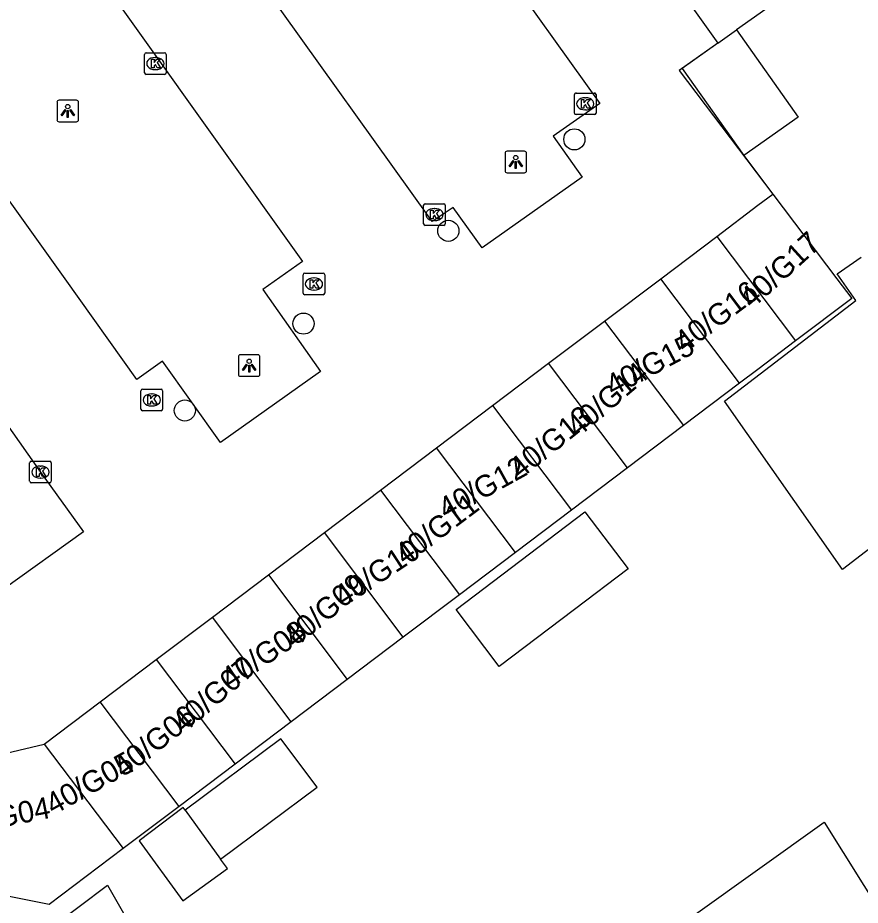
# Model space of a CAD drawing. Extents: x 161845 to 162341, y 381620 to 382158.
# Drawn here: x 161965.76 to 162004.73, y 381971.03 to 382012.07 of the extents above; entities that cross this region are included whole.
import ezdxf

# ---------------------------------------------------------------- set-up
doc = ezdxf.new("R2010")
doc.units = 0
for name, color, linetype in [('IMGEO_Boom', 7, 'Continuous'), ('IMGEO_Kolk', 7, 'Continuous'), ('IMGEO_Lichtpunt', 7, 'Continuous'), ('IMGEO_Muur', 7, 'Continuous'), ('IMGEO_Pand', 7, 'Continuous'), ('IMGEO_Pand_nummerreeks', 7, 'Continuous'), ('IMGEO_Rijbaan_lokaal_open', 7, 'Continuous')]:
    doc.layers.add(name, color=color, linetype=linetype)

msp = doc.modelspace()

# ---------------------------------------------------------------- linework, layer by layer
at = {"layer": 'IMGEO_Boom'}
for centre in [(161991.507, 382006.447), (161985.677, 382002.219), (161978.975, 381997.927), (161973.486, 381993.909)]:
    msp.add_circle(centre, 0.489, dxfattribs=at)
at = {"layer": 'IMGEO_Kolk'}
for p, q in [((161971.621, 382009.529), (161971.621, 382010.381)), ((161971.696, 382010.455), (161972.548, 382010.455)), ((161972.109, 382010.235), (161972.134, 382010.235)), ((161972.622, 382010.381), (161972.622, 382009.529)), ((161972.548, 382009.455), (161971.696, 382009.455)), ((161972.132, 382009.675), (161972.107, 382009.675)), ((161991.584, 382008.593), (161992.436, 382008.593)), ((161991.509, 382007.667), (161991.509, 382008.519)), ((161991.997, 382008.373), (161992.022, 382008.373)), ((161992.51, 382008.519), (161992.51, 382007.667)), ((161992.02, 382007.813), (161991.995, 382007.813)), ((161992.436, 382007.593), (161991.584, 382007.593)), ((161984.535, 382002.546), (161984.535, 382003.398)), ((161984.61, 382003.472), (161985.462, 382003.472)), ((161985.023, 382003.252), (161985.048, 382003.252)), ((161985.536, 382003.398), (161985.536, 382002.546)), ((161985.462, 382002.472), (161984.61, 382002.472)), ((161985.046, 382002.692), (161985.021, 382002.692)), ((161978.96, 381999.334), (161978.96, 382000.186)), ((161979.035, 382000.26), (161979.887, 382000.26)), ((161979.448, 382000.04), (161979.473, 382000.04)), ((161979.961, 382000.186), (161979.961, 381999.334)), ((161979.887, 381999.26), (161979.035, 381999.26)), ((161979.471, 381999.48), (161979.446, 381999.48)), ((161971.458, 381993.971), (161971.458, 381994.823)), ((161971.533, 381994.897), (161972.385, 381994.897)), ((161971.946, 381994.677), (161971.971, 381994.677)), ((161972.459, 381994.823), (161972.459, 381993.971)), ((161972.385, 381993.897), (161971.533, 381993.897)), ((161971.969, 381994.117), (161971.944, 381994.117)), ((161966.308, 381990.635), (161966.308, 381991.487)), ((161966.383, 381991.561), (161967.235, 381991.561)), ((161966.796, 381991.341), (161966.821, 381991.341)), ((161967.309, 381991.487), (161967.309, 381990.635)), ((161967.235, 381990.561), (161966.383, 381990.561)), ((161966.819, 381990.781), (161966.794, 381990.781))]:
    msp.add_line(p, q, dxfattribs=at)
for points in [[(161971.621, 382009.529), (161971.621, 382010.381)], [(161971.696, 382010.455), (161972.548, 382010.455)], [(161972.622, 382010.381), (161972.622, 382009.529)], [(161971.942, 382010.155), (161972.065, 382010.155), (161972.065, 382010.004), (161972.195, 382010.155), (161972.359, 382010.155), (161972.213, 382010.004), (161972.366, 382009.755), (161972.214, 382009.755), (161972.129, 382009.919), (161972.065, 382009.852), (161972.065, 382009.755), (161971.942, 382009.755), (161971.942, 382010.155)], [(161972.548, 382009.455), (161971.696, 382009.455)], [(161991.584, 382008.593), (161992.436, 382008.593)], [(161991.509, 382007.667), (161991.509, 382008.519)], [(161991.83, 382008.293), (161991.953, 382008.293), (161991.953, 382008.142), (161992.083, 382008.293), (161992.247, 382008.293), (161992.101, 382008.142), (161992.254, 382007.893), (161992.102, 382007.893), (161992.017, 382008.057), (161991.953, 382007.99), (161991.953, 382007.893), (161991.83, 382007.893), (161991.83, 382008.293)], [(161992.51, 382008.519), (161992.51, 382007.667)], [(161992.436, 382007.593), (161991.584, 382007.593)], [(161984.535, 382002.546), (161984.535, 382003.398)], [(161984.61, 382003.472), (161985.462, 382003.472)], [(161985.536, 382003.398), (161985.536, 382002.546)], [(161984.856, 382003.172), (161984.979, 382003.172), (161984.979, 382003.021), (161985.109, 382003.172), (161985.273, 382003.172), (161985.127, 382003.021), (161985.28, 382002.772), (161985.128, 382002.772), (161985.043, 382002.936), (161984.979, 382002.869), (161984.979, 382002.772), (161984.856, 382002.772), (161984.856, 382003.172)], [(161985.462, 382002.472), (161984.61, 382002.472)], [(161978.96, 381999.334), (161978.96, 382000.186)], [(161979.035, 382000.26), (161979.887, 382000.26)], [(161979.281, 381999.96), (161979.404, 381999.96), (161979.404, 381999.809), (161979.534, 381999.96), (161979.698, 381999.96), (161979.552, 381999.809), (161979.705, 381999.56), (161979.553, 381999.56), (161979.468, 381999.724), (161979.404, 381999.657), (161979.404, 381999.56), (161979.281, 381999.56), (161979.281, 381999.96)], [(161979.961, 382000.186), (161979.961, 381999.334)], [(161979.887, 381999.26), (161979.035, 381999.26)], [(161971.458, 381993.971), (161971.458, 381994.823)], [(161971.533, 381994.897), (161972.385, 381994.897)], [(161972.459, 381994.823), (161972.459, 381993.971)], [(161971.779, 381994.597), (161971.902, 381994.597), (161971.902, 381994.446), (161972.032, 381994.597), (161972.196, 381994.597), (161972.05, 381994.446), (161972.203, 381994.197), (161972.051, 381994.197), (161971.966, 381994.361), (161971.902, 381994.294), (161971.902, 381994.197), (161971.779, 381994.197), (161971.779, 381994.597)], [(161972.385, 381993.897), (161971.533, 381993.897)], [(161966.308, 381990.635), (161966.308, 381991.487)], [(161966.383, 381991.561), (161967.235, 381991.561)], [(161967.309, 381991.487), (161967.309, 381990.635)], [(161966.629, 381991.261), (161966.752, 381991.261), (161966.752, 381991.11), (161966.882, 381991.261), (161967.046, 381991.261), (161966.9, 381991.11), (161967.053, 381990.861), (161966.901, 381990.861), (161966.816, 381991.025), (161966.752, 381990.958), (161966.752, 381990.861), (161966.629, 381990.861), (161966.629, 381991.261)], [(161967.235, 381990.561), (161966.383, 381990.561)]]:
    msp.add_lwpolyline(points, dxfattribs=at)
for centre, start, end in [((161971.698, 382010.379), 91.552, 178.448), ((161971.698, 382010.379), 91.552, 178.448), ((161972.546, 382010.379), 1.552, 88.448), ((161972.546, 382010.379), 1.552, 88.448), ((161971.698, 382009.531), 181.552, 268.448), ((161971.698, 382009.531), 181.552, 268.448), ((161972.546, 382009.531), 271.552, 358.448), ((161972.546, 382009.531), 271.552, 358.448), ((161991.586, 382008.517), 91.552, 178.448), ((161991.586, 382008.517), 91.552, 178.448), ((161992.434, 382008.517), 1.552, 88.448), ((161992.434, 382008.517), 1.552, 88.448), ((161991.586, 382007.669), 181.552, 268.448), ((161991.586, 382007.669), 181.552, 268.448), ((161992.434, 382007.669), 271.552, 358.448), ((161992.434, 382007.669), 271.552, 358.448), ((161984.612, 382003.396), 91.552, 178.448), ((161984.612, 382003.396), 91.552, 178.448), ((161985.46, 382003.396), 1.552, 88.448), ((161985.46, 382003.396), 1.552, 88.448), ((161984.612, 382002.548), 181.552, 268.448), ((161984.612, 382002.548), 181.552, 268.448), ((161985.46, 382002.548), 271.552, 358.448), ((161985.46, 382002.548), 271.552, 358.448), ((161979.037, 382000.184), 91.552, 178.448), ((161979.037, 382000.184), 91.552, 178.448), ((161979.885, 382000.184), 1.552, 88.448), ((161979.885, 382000.184), 1.552, 88.448), ((161979.037, 381999.336), 181.552, 268.448), ((161979.037, 381999.336), 181.552, 268.448), ((161979.885, 381999.336), 271.552, 358.448), ((161979.885, 381999.336), 271.552, 358.448), ((161971.535, 381994.821), 91.552, 178.448), ((161971.535, 381994.821), 91.552, 178.448), ((161972.383, 381994.821), 1.552, 88.448), ((161972.383, 381994.821), 1.552, 88.448), ((161971.535, 381993.973), 181.552, 268.448), ((161971.535, 381993.973), 181.552, 268.448), ((161972.383, 381993.973), 271.552, 358.448), ((161972.383, 381993.973), 271.552, 358.448), ((161966.385, 381991.485), 91.552, 178.448), ((161966.385, 381991.485), 91.552, 178.448), ((161967.233, 381991.485), 1.552, 88.448), ((161967.233, 381991.485), 1.552, 88.448), ((161966.385, 381990.637), 181.552, 268.448), ((161966.385, 381990.637), 181.552, 268.448), ((161967.233, 381990.637), 271.552, 358.448), ((161967.233, 381990.637), 271.552, 358.448)]:
    msp.add_arc(centre, 0.0765, start, end, dxfattribs=at)
for centre, major_axis, ratio, start_param, end_param in [((161972.108, 382009.955), (-0.387, 0.002), 0.722429, 4.712389, 7.853982), ((161972.133, 382009.955), (-0.39, 0.002), 0.717154, 1.570796, 4.712389), ((161991.996, 382008.093), (-0.387, 0.002), 0.722429, 4.712389, 7.853982), ((161992.021, 382008.093), (-0.39, 0.002), 0.717154, 1.570796, 4.712389), ((161985.022, 382002.972), (-0.387, 0.002), 0.722429, 4.712389, 7.853982), ((161985.047, 382002.972), (-0.39, 0.002), 0.717154, 1.570796, 4.712389), ((161979.447, 381999.76), (-0.387, 0.002), 0.722429, 4.712389, 7.853982), ((161979.472, 381999.76), (-0.39, 0.002), 0.717154, 1.570796, 4.712389), ((161971.945, 381994.397), (-0.387, 0.002), 0.722429, 4.712389, 7.853982), ((161971.97, 381994.397), (-0.39, 0.002), 0.717154, 1.570796, 4.712389), ((161966.795, 381991.061), (-0.387, 0.002), 0.722429, 4.712389, 7.853982), ((161966.82, 381991.061), (-0.39, 0.002), 0.717154, 1.570796, 4.712389)]:
    msp.add_ellipse(centre, major_axis=major_axis, ratio=ratio, start_param=start_param, end_param=end_param, dxfattribs=at)
at = {"layer": 'IMGEO_Lichtpunt'}
for p, q in [((161967.573, 382008.166), (161967.573, 382007.359)), ((161967.573, 382008.166), (161967.573, 382007.359)), ((161968.475, 382008.261), (161967.667, 382008.261)), ((161968.475, 382008.261), (161967.667, 382008.261)), ((161968.569, 382007.359), (161968.569, 382008.166)), ((161968.569, 382007.359), (161968.569, 382008.166)), ((161967.667, 382007.265), (161968.475, 382007.265)), ((161967.667, 382007.265), (161968.475, 382007.265)), ((161988.299, 382005.807), (161988.299, 382005)), ((161988.299, 382005.807), (161988.299, 382005)), ((161989.201, 382005.902), (161988.393, 382005.902)), ((161989.201, 382005.902), (161988.393, 382005.902)), ((161989.295, 382005), (161989.295, 382005.807)), ((161989.295, 382005), (161989.295, 382005.807)), ((161988.393, 382004.906), (161989.201, 382004.906)), ((161988.393, 382004.906), (161989.201, 382004.906)), ((161975.964, 381996.391), (161975.964, 381995.584)), ((161975.964, 381996.391), (161975.964, 381995.584)), ((161976.866, 381996.486), (161976.058, 381996.486)), ((161976.866, 381996.486), (161976.058, 381996.486)), ((161976.96, 381995.584), (161976.96, 381996.391)), ((161976.96, 381995.584), (161976.96, 381996.391)), ((161976.058, 381995.49), (161976.866, 381995.49)), ((161976.058, 381995.49), (161976.866, 381995.49))]:
    msp.add_line(p, q, dxfattribs=at)
for points in [[(161967.947, 382007.83), (161967.986, 382007.802), (161967.798, 382007.54), (161967.76, 382007.567), (161967.947, 382007.83)], [(161968.049, 382007.782), (161968.096, 382007.782), (161968.096, 382007.46), (161968.049, 382007.46), (161968.049, 382007.782)], [(161968.159, 382007.802), (161968.197, 382007.829), (161968.384, 382007.567), (161968.345, 382007.539), (161968.159, 382007.802)], [(161988.673, 382005.471), (161988.712, 382005.443), (161988.524, 382005.181), (161988.486, 382005.208), (161988.673, 382005.471)], [(161988.775, 382005.423), (161988.822, 382005.423), (161988.822, 382005.101), (161988.775, 382005.101), (161988.775, 382005.423)], [(161988.885, 382005.443), (161988.923, 382005.47), (161989.11, 382005.208), (161989.071, 382005.18), (161988.885, 382005.443)], [(161976.338, 381996.055), (161976.377, 381996.027), (161976.189, 381995.765), (161976.151, 381995.792), (161976.338, 381996.055)], [(161976.44, 381996.007), (161976.487, 381996.007), (161976.487, 381995.685), (161976.44, 381995.685), (161976.44, 381996.007)], [(161976.55, 381996.027), (161976.588, 381996.054), (161976.775, 381995.792), (161976.736, 381995.764), (161976.55, 381996.027)]]:
    msp.add_lwpolyline(points, dxfattribs=at)
for centre in [(161968.072, 382007.964), (161988.798, 382005.605), (161976.463, 381996.189)]:
    msp.add_circle(centre, 0.0994, dxfattribs=at)
for centre, start, end in [((161967.667, 382008.166), 90, 180), ((161967.667, 382008.166), 90, 180), ((161968.475, 382008.166), 0, 90), ((161968.475, 382008.166), 0, 90), ((161967.667, 382007.359), 180, 270), ((161967.667, 382007.359), 180, 270), ((161968.475, 382007.359), 270, 0), ((161968.475, 382007.359), 270, 360), ((161988.393, 382005.807), 90, 180), ((161988.393, 382005.807), 90, 180), ((161989.201, 382005.807), 0, 90), ((161989.201, 382005.807), 0, 90), ((161988.393, 382005), 180, 270), ((161988.393, 382005), 180, 270), ((161989.201, 382005), 270, 0), ((161989.201, 382005), 270, 360), ((161976.058, 381996.391), 90, 180), ((161976.058, 381996.391), 90, 180), ((161976.866, 381996.391), 0, 90), ((161976.866, 381996.391), 0, 90), ((161976.058, 381995.584), 180, 270), ((161976.058, 381995.584), 180, 270), ((161976.866, 381995.584), 270, 0), ((161976.866, 381995.584), 270, 360)]:
    msp.add_arc(centre, 0.0946, start, end, dxfattribs=at)
at = {"layer": 'IMGEO_Muur'}
msp.add_lwpolyline([(161998.137, 382010.902), (161996.361, 382009.629), (162000.686, 382003.921)], dxfattribs=at)
at = {"layer": 'IMGEO_Pand'}
for points in [[(162000.99, 382017.333), (162003.079, 382014.393), (161999.002, 382011.513)], [(161996.058, 382013.827), (161998.137, 382010.902)], [(161998.137, 382010.902), (161999.002, 382011.513)], [(161999.002, 382011.513), (162001.865, 382007.483), (161999.348, 382005.705)], [(161998.137, 382010.902), (161996.492, 382009.723), (161999.348, 382005.705)], [(161998.094, 382001.963), (162000.001, 382003.403), (162000.686, 382003.921)], [(162000.686, 382003.921), (162003.65, 382000), (162004.343, 381999.083), (162001.745, 381997.127)], [(161995.501, 382000.006), (161998.094, 382001.963)], [(161998.094, 382001.963), (162001.745, 381997.127)], [(162010.905, 381991.921), (162003.909, 381986.55), (161998.457, 381994.338), (162004.528, 381998.999), (162003.669, 382000.227), (162004.777, 382001.002)], [(161992.908, 381998.048), (161995.501, 382000.006)], [(161999.151, 381995.172), (161995.501, 382000.006)], [(161990.316, 381996.091), (161992.908, 381998.048)], [(161992.908, 381998.048), (161996.558, 381993.215)], [(162001.745, 381997.127), (162000, 381995.813), (161999.151, 381995.172)], [(161987.723, 381994.134), (161990.316, 381996.091)], [(161993.965, 381991.258), (161990.316, 381996.091)], [(161999.151, 381995.172), (161996.558, 381993.215)], [(161985.13, 381992.176), (161987.723, 381994.134)], [(161987.723, 381994.134), (161991.372, 381989.301)], [(161996.558, 381993.215), (161993.965, 381991.258)], [(161982.538, 381990.219), (161985.13, 381992.176)], [(161988.779, 381987.344), (161985.13, 381992.176)], [(161993.965, 381991.258), (161991.372, 381989.301)], [(161979.945, 381988.261), (161982.538, 381990.219)], [(161982.538, 381990.219), (161986.186, 381985.386)], [(161991.372, 381989.301), (161988.779, 381987.344)], [(161991.999, 381989.224), (161993.998, 381986.582), (161991.52, 381984.707), (161988.036, 381982.071), (161986.037, 381984.713), (161991.999, 381989.224)], [(161977.352, 381986.304), (161979.945, 381988.261)], [(161983.593, 381983.429), (161979.945, 381988.261)], [(161988.779, 381987.344), (161986.186, 381985.386)], [(161974.76, 381984.346), (161977.352, 381986.304)], [(161977.352, 381986.304), (161981, 381981.472)], [(161986.186, 381985.386), (161983.593, 381983.429)], [(161972.167, 381982.389), (161974.76, 381984.346)], [(161978.407, 381979.515), (161974.76, 381984.346)], [(161983.593, 381983.429), (161981, 381981.472)], [(161969.575, 381980.431), (161972.167, 381982.389)], [(161972.167, 381982.389), (161975.815, 381977.558)], [(161981, 381981.472), (161978.407, 381979.515)], [(161966.982, 381978.474), (161969.575, 381980.431)], [(161973.222, 381975.601), (161969.575, 381980.431)], [(161978.407, 381979.515), (161975.815, 381977.558)], [(161975.144, 381973.157), (161979.601, 381976.482), (161977.925, 381978.729), (161973.495, 381975.424)], [(161964.038, 381977.776), (161966.982, 381978.474)], [(161966.982, 381978.474), (161970.629, 381973.644)], [(161975.815, 381977.558), (161973.222, 381975.601)], [(161973.222, 381975.601), (161970.629, 381973.644)], [(161973.495, 381975.424), (161973.405, 381975.547), (161971.373, 381974.013), (161973.395, 381971.235), (161975.453, 381972.733), (161975.144, 381973.157)], [(161973.495, 381975.424), (161975.144, 381973.157)], [(162004.459, 381960.074), (162001.557, 381964.146), (162000, 381966.33), (161999.916, 381966.448), (161996.996, 381970.544), (162003.07, 381974.874), (162005.776, 381970.545)], [(161970.629, 381973.644), (161967.212, 381971.065), (161962.878, 381971.924)], [(161969.903, 381971.952), (161971.646, 381968.899), (161969.046, 381966.936), (161967.29, 381969.979), (161969.903, 381971.952)]]:
    msp.add_lwpolyline(points, dxfattribs=at)
at = {"layer": 'IMGEO_Rijbaan_lokaal_open'}
for points in [[(161979.786, 382019.783), (161982.783, 382021.938), (161992.688, 382008.112), (161990.532, 382006.599), (161991.862, 382004.7), (161987.238, 382001.431), (161985.902, 382003.305), (161984.93, 382002.653), (161984.823, 382002.808), (161977.157, 382013.523), (161970.462, 382023.018)], [(161967.222, 382016.789), (161967.422, 382016.928), (161978.923, 382000.803), (161977.102, 381999.506), (161979.77, 381995.72), (161975.138, 381992.428), (161972.459, 381996.184), (161971.271, 381995.35), (161967.947, 382000), (161952.913, 382021.03)], [(161949.468, 382015.472), (161953.016, 382010.449), (161959.531, 382001.364), (161960.495, 382000), (161966.81, 381991.062), (161968.8, 381988.304), (161965.15, 381985.684), (161964.923, 381986.014)], [(161999.348, 382005.705), (162000.686, 382003.921)]]:
    msp.add_lwpolyline(points, dxfattribs=at)

# ---------------------------------------------------------------- texts
at = {"layer": 'IMGEO_Pand_nummerreeks'}
for s, rotation, p in [('40/G17', 42.2737, (161999.728, 381998.574)), ('40/G16', 37.1169, (161996.619, 381996.544)), ('40/G15', 28.0725, (161993.29, 381994.539)), ('40/G14', 40.4622, (161991.674, 381992.627)), ('40/G13', 38.6598, (161988.989, 381990.694)), ('40/G12', 28.9264, (161985.567, 381988.848)), ('40/G11', 36.8699, (161983.675, 381986.725)), ('40/G10', 33.3407, (161980.809, 381984.786)), ('40/G09', 39.8056, (161978.573, 381982.884)), ('40/G08', 34.0459, (161975.588, 381980.99)), ('40/G07', 40.6013, (161973.438, 381978.943)), ('40/G06', 38.0888, (161970.663, 381976.879)), ('40/G05', 29.1676, (161967.401, 381975.178)), ('40/G04', 11.0702, (161963.022, 381974.234))]:
    msp.add_text(s, height=1, rotation=rotation, dxfattribs=at).set_placement(p)

doc.saveas('drawing.dxf')
